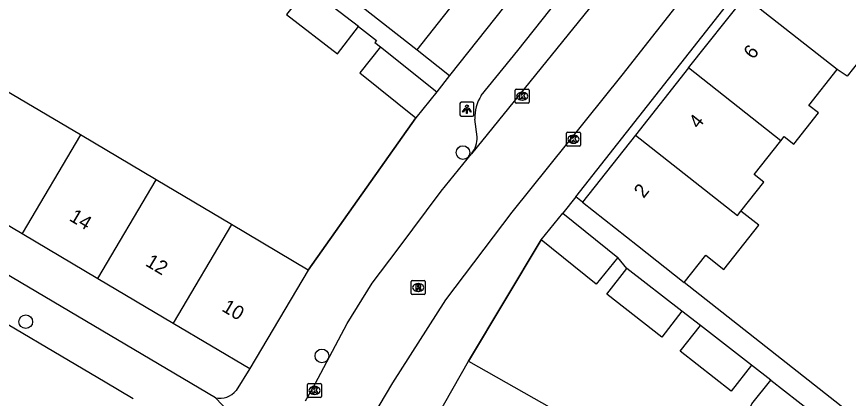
# Model space of a CAD drawing. Extents: x 160026 to 161302, y 384757 to 385701.
# Drawn here: x 160366.7 to 160426.3, y 385107 to 385134.3 of the extents above; entities that cross this region are included whole.
import ezdxf

# ---------------------------------------------------------------- set-up
doc = ezdxf.new("R2010")
doc.units = 0
for name, color, linetype in [('IMGEO_Boom', 7, 'Continuous'), ('IMGEO_Kolk', 7, 'Continuous'), ('IMGEO_Lichtpunt', 7, 'Continuous'), ('IMGEO_Muur', 7, 'Continuous'), ('IMGEO_Pand', 7, 'Continuous'), ('IMGEO_Pand_nummerreeks', 7, 'Continuous'), ('IMGEO_Rijbaan_lokaal_gesloten', 7, 'Continuous'), ('IMGEO_Rijbaan_lokaal_open', 7, 'Continuous'), ('IMGEO_Rioolput', 7, 'Continuous'), ('IMGEO_Voetpad_open', 7, 'Continuous')]:
    doc.layers.add(name, color=color, linetype=linetype)

msp = doc.modelspace()

# ---------------------------------------------------------------- linework, layer by layer
at = {"layer": 'IMGEO_Boom'}
for centre in [(160398.678, 385124.57), (160367.392, 385112.466), (160388.586, 385110.018)]:
    msp.add_circle(centre, 0.489, dxfattribs=at)
at = {"layer": 'IMGEO_Kolk'}
for p, q in [((160402.417, 385128.182), (160402.417, 385129.034)), ((160402.492, 385129.108), (160403.344, 385129.108)), ((160402.905, 385128.888), (160402.93, 385128.888)), ((160403.418, 385129.034), (160403.418, 385128.182)), ((160403.344, 385128.108), (160402.492, 385128.108)), ((160402.928, 385128.328), (160402.903, 385128.328)), ((160406.082, 385125.096), (160406.082, 385125.948)), ((160406.157, 385126.022), (160407.009, 385126.022)), ((160406.57, 385125.802), (160406.595, 385125.802)), ((160407.083, 385125.948), (160407.083, 385125.096)), ((160406.593, 385125.242), (160406.568, 385125.242)), ((160407.009, 385125.022), (160406.157, 385125.022)), ((160387.558, 385107.12), (160387.558, 385107.972)), ((160387.633, 385108.046), (160388.485, 385108.046)), ((160388.046, 385107.826), (160388.071, 385107.826)), ((160388.559, 385107.972), (160388.559, 385107.12)), ((160388.069, 385107.266), (160388.044, 385107.266)), ((160388.485, 385107.046), (160387.633, 385107.046))]:
    msp.add_line(p, q, dxfattribs=at)
for points in [[(160402.417, 385128.182), (160402.417, 385129.034)], [(160402.492, 385129.108), (160403.344, 385129.108)], [(160402.738, 385128.808), (160402.861, 385128.808), (160402.861, 385128.657), (160402.991, 385128.808), (160403.155, 385128.808), (160403.009, 385128.657), (160403.162, 385128.408), (160403.01, 385128.408), (160402.925, 385128.572), (160402.861, 385128.505), (160402.861, 385128.408), (160402.738, 385128.408), (160402.738, 385128.808)], [(160403.418, 385129.034), (160403.418, 385128.182)], [(160403.344, 385128.108), (160402.492, 385128.108)], [(160406.082, 385125.096), (160406.082, 385125.948)], [(160406.157, 385126.022), (160407.009, 385126.022)], [(160406.403, 385125.722), (160406.526, 385125.722), (160406.526, 385125.571), (160406.656, 385125.722), (160406.82, 385125.722), (160406.674, 385125.571), (160406.827, 385125.322), (160406.675, 385125.322), (160406.59, 385125.486), (160406.526, 385125.419), (160406.526, 385125.322), (160406.403, 385125.322), (160406.403, 385125.722)], [(160407.083, 385125.948), (160407.083, 385125.096)], [(160407.009, 385125.022), (160406.157, 385125.022)], [(160387.558, 385107.12), (160387.558, 385107.972)], [(160387.633, 385108.046), (160388.485, 385108.046)], [(160388.559, 385107.972), (160388.559, 385107.12)], [(160387.879, 385107.746), (160388.002, 385107.746), (160388.002, 385107.595), (160388.132, 385107.746), (160388.296, 385107.746), (160388.15, 385107.595), (160388.303, 385107.346), (160388.151, 385107.346), (160388.066, 385107.51), (160388.002, 385107.443), (160388.002, 385107.346), (160387.879, 385107.346), (160387.879, 385107.746)], [(160388.485, 385107.046), (160387.633, 385107.046)]]:
    msp.add_lwpolyline(points, dxfattribs=at)
for centre, start, end in [((160402.494, 385129.032), 91.55205, 178.44795), ((160402.494, 385129.032), 91.55205, 178.44795), ((160403.342, 385129.032), 1.55205, 88.44795), ((160403.342, 385129.032), 1.55205, 88.44795), ((160402.494, 385128.184), 181.55205, 268.44795), ((160402.494, 385128.184), 181.55205, 268.44795), ((160403.342, 385128.184), 271.55205, 358.44795), ((160403.342, 385128.184), 271.55205, 358.44795), ((160406.159, 385125.946), 91.55205, 178.44795), ((160406.159, 385125.946), 91.55205, 178.44795), ((160407.007, 385125.946), 1.55205, 88.44795), ((160407.007, 385125.946), 1.55205, 88.44795), ((160406.159, 385125.098), 181.55205, 268.44795), ((160406.159, 385125.098), 181.55205, 268.44795), ((160407.007, 385125.098), 271.55205, 358.44795), ((160407.007, 385125.098), 271.55205, 358.44795), ((160387.635, 385107.97), 91.55205, 178.44795), ((160387.635, 385107.97), 91.55205, 178.44795), ((160388.483, 385107.97), 1.55205, 88.44795), ((160388.483, 385107.97), 1.55205, 88.44795), ((160387.635, 385107.122), 181.55205, 268.44795), ((160387.635, 385107.122), 181.55205, 268.44795), ((160388.483, 385107.122), 271.55205, 358.44795), ((160388.483, 385107.122), 271.55205, 358.44795)]:
    msp.add_arc(centre, 0.0765, start, end, dxfattribs=at)
for centre, major_axis, ratio, start_param, end_param in [((160402.904, 385128.608), (-0.387, 0.002), 0.722429, 4.712389, 7.853982), ((160402.929, 385128.608), (-0.39, 0.002), 0.717154, 1.570796, 4.712389), ((160406.569, 385125.522), (-0.387, 0.002), 0.722429, 4.712389, 7.853982), ((160406.594, 385125.522), (-0.39, 0.002), 0.717154, 1.570796, 4.712389), ((160388.045, 385107.546), (-0.387, 0.002), 0.722429, 4.712389, 7.853982), ((160388.07, 385107.546), (-0.39, 0.002), 0.717154, 1.570796, 4.712389)]:
    msp.add_ellipse(centre, major_axis=major_axis, ratio=ratio, start_param=start_param, end_param=end_param, dxfattribs=at)
at = {"layer": 'IMGEO_Lichtpunt'}
for p, q in [((160398.464, 385128.079), (160398.464, 385127.272)), ((160398.464, 385128.079), (160398.464, 385127.272)), ((160399.366, 385128.174), (160398.558, 385128.174)), ((160399.366, 385128.174), (160398.558, 385128.174)), ((160399.46, 385127.272), (160399.46, 385128.079)), ((160399.46, 385127.272), (160399.46, 385128.079)), ((160398.558, 385127.178), (160399.366, 385127.178)), ((160398.558, 385127.178), (160399.366, 385127.178))]:
    msp.add_line(p, q, dxfattribs=at)
for points in [[(160398.838, 385127.743), (160398.877, 385127.715), (160398.689, 385127.453), (160398.651, 385127.48), (160398.838, 385127.743)], [(160398.94, 385127.695), (160398.987, 385127.695), (160398.987, 385127.373), (160398.94, 385127.373), (160398.94, 385127.695)], [(160399.05, 385127.715), (160399.088, 385127.742), (160399.275, 385127.48), (160399.236, 385127.452), (160399.05, 385127.715)]]:
    msp.add_lwpolyline(points, dxfattribs=at)
msp.add_circle((160398.963, 385127.877), 0.0994, dxfattribs=at)
for centre, start, end in [((160398.558, 385128.079), 90, 180), ((160398.558, 385128.079), 90, 180), ((160399.366, 385128.079), 0, 90), ((160399.366, 385128.079), 0, 90), ((160398.558, 385127.272), 180, 270), ((160398.558, 385127.272), 180, 270), ((160399.366, 385127.272), 270, 0), ((160399.366, 385127.272), 270, 360)]:
    msp.add_arc(centre, 0.0946, start, end, dxfattribs=at)
at = {"layer": 'IMGEO_Muur'}
for points in [[(160387.606, 385116.164), (160395.316, 385127.065)], [(160399.08, 385109.636), (160404.28, 385118.318)]]:
    msp.add_lwpolyline(points, dxfattribs=at)
at = {"layer": 'IMGEO_Pand'}
for points in [[(160388.899, 385136.994), (160391.469, 385134.988), (160395.41, 385131.912)], [(160387.574, 385136.374), (160386.049, 385134.443), (160389.705, 385131.638), (160391.203, 385133.589)], [(160391.203, 385133.589), (160387.574, 385136.374)], [(160395.41, 385131.912), (160399.257, 385136.84)], [(160414.825, 385130.622), (160418.852, 385135.725)], [(160425.462, 385130.507), (160418.852, 385135.725)], [(160429.474, 385135.723), (160427.258, 385132.915), (160427.989, 385132.338), (160426.18, 385130.045), (160425.462, 385130.507)], [(160392.78, 385132.125), (160391.3, 385130.27), (160395.316, 385127.065)], [(160392.78, 385132.125), (160396.797, 385128.92)], [(160414.825, 385130.622), (160411.029, 385125.813)], [(160421.417, 385125.418), (160414.825, 385130.622)], [(160421.417, 385125.418), (160421.658, 385125.723), (160422.352, 385125.174), (160424.112, 385127.404), (160423.435, 385127.938), (160425.462, 385130.507)], [(160371.303, 385125.827), (160366.008, 385128.966)], [(160396.797, 385128.92), (160395.316, 385127.065)], [(160371.303, 385125.827), (160367.143, 385118.768)], [(160376.718, 385122.618), (160371.303, 385125.827)], [(160411.029, 385125.813), (160407.24, 385121.013)], [(160411.029, 385125.813), (160418.32, 385120.058), (160418.565, 385120.369)], [(160418.565, 385120.369), (160420.213, 385122.455), (160419.514, 385123.007), (160421.417, 385125.418)], [(160372.558, 385115.558), (160376.718, 385122.618)], [(160382.108, 385119.423), (160376.718, 385122.618)], [(160361.848, 385121.906), (160367.143, 385118.768)], [(160407.24, 385121.013), (160411.164, 385117.915), (160414.516, 385115.27)], [(160414.516, 385115.27), (160416.06, 385117.227), (160417.35, 385116.209), (160419.84, 385119.363), (160418.565, 385120.369)], [(160404.28, 385118.318), (160405.818, 385120.228)], [(160405.818, 385120.228), (160409.747, 385117.063)], [(160382.108, 385119.423), (160377.947, 385112.363)], [(160387.606, 385116.164), (160382.108, 385119.423)], [(160367.143, 385118.768), (160372.558, 385115.558)], [(160409.747, 385117.063), (160408.208, 385115.153), (160404.28, 385118.318)], [(160387.606, 385116.164), (160383.427, 385109.115)], [(160414.35, 385113.209), (160412.914, 385111.361), (160408.969, 385114.427), (160410.406, 385116.271)], [(160414.35, 385113.209), (160410.406, 385116.271)], [(160372.558, 385115.558), (160377.947, 385112.363)], [(160377.947, 385112.363), (160383.427, 385109.115)], [(160419.313, 385109.352), (160417.877, 385107.504), (160414.212, 385110.352), (160415.669, 385112.184)], [(160419.313, 385109.352), (160415.669, 385112.184)], [(160395.003, 385102.463), (160399.08, 385109.636)], [(160399.08, 385109.636), (160405.009, 385106.266)], [(160424.617, 385105.23), (160423.181, 385103.383), (160419.269, 385106.422), (160419.357, 385106.577), (160420.704, 385108.271)], [(160420.704, 385108.271), (160424.617, 385105.23)]]:
    msp.add_lwpolyline(points, dxfattribs=at)
at = {"layer": 'IMGEO_Rijbaan_lokaal_gesloten'}
msp.add_lwpolyline([(160333.972, 385131.862), (160342.253, 385126.595), (160343.306, 385125.926), (160345.516, 385124.585), (160353.245, 385119.896), (160362.963, 385114.135), (160373.082, 385108.155), (160375.076, 385106.975)], dxfattribs=at)
at = {"layer": 'IMGEO_Rijbaan_lokaal_open'}
for points in [[(160448.926, 385179.255), (160441.301, 385169.642), (160436.8, 385163.928), (160428.03, 385152.903), (160419.879, 385142.636), (160410.04, 385130.111), (160402.173, 385120.293), (160397.425, 385114.032), (160393.624, 385108.1), (160392.655, 385106.45), (160391.867, 385105.123), (160391.174, 385103.832)], [(160442.328, 385178.803), (160425.568, 385157.508), (160410.374, 385138.189), (160399.293, 385124.481)], [(160387.414, 385106.8), (160388.11, 385108.029), (160390.397, 385112.327), (160392.191, 385115.214), (160394.033, 385117.675), (160397.127, 385121.806), (160399.293, 385124.481)]]:
    msp.add_lwpolyline(points, dxfattribs=at)
at = {"layer": 'IMGEO_Rioolput'}
for p, q in [((160394.975, 385114.485), (160394.975, 385115.337)), ((160395.05, 385115.411), (160395.902, 385115.411)), ((160395.463, 385115.191), (160395.488, 385115.191)), ((160395.976, 385115.337), (160395.976, 385114.485)), ((160395.902, 385114.411), (160395.05, 385114.411)), ((160395.486, 385114.631), (160395.461, 385114.631))]:
    msp.add_line(p, q, dxfattribs=at)
for points in [[(160394.975, 385114.485), (160394.975, 385115.337)], [(160395.05, 385115.411), (160395.902, 385115.411)], [(160395.564, 385115.109), (160395.312, 385115.111), (160395.312, 385114.711)], [(160395.49, 385115.03), (160395.436, 385115.03), (160395.436, 385114.949)], [(160395.436, 385114.949), (160395.488, 385114.949)], [(160395.976, 385115.337), (160395.976, 385114.485)], [(160395.902, 385114.411), (160395.05, 385114.411)], [(160395.312, 385114.711), (160395.436, 385114.711), (160395.436, 385114.873), (160395.447, 385114.873)], [(160395.494, 385114.844), (160395.565, 385114.711), (160395.705, 385114.711), (160395.64, 385114.837)]]:
    msp.add_lwpolyline(points, dxfattribs=at)
for centre, radius, start, end in [((160395.052, 385115.335), 0.0765, 91.55205, 178.44795), ((160395.052, 385115.335), 0.0765, 91.55205, 178.44795), ((160395.472, 385115.138), 0.19, 274.7715, 282.96867), ((160395.496, 385114.934), 0.0964, 77.00612, 93.18647), ((160395.51, 385114.991), 0.0378, 276.66336, 79.67722), ((160395.563, 385114.999), 0.109, 350.36119, 89.41601), ((160395.561, 385114.999), 0.112, 277.58423, 350.98172), ((160395.9, 385115.335), 0.0765, 1.55205, 88.44795), ((160395.9, 385115.335), 0.0765, 1.55205, 88.44795), ((160395.052, 385114.487), 0.0765, 181.55205, 268.44795), ((160395.052, 385114.487), 0.0765, 181.55205, 268.44795), ((160395.446, 385114.82), 0.0533, 26.02933, 88.69889), ((160395.545, 385114.784), 0.108, 29.51342, 73.79051), ((160395.9, 385114.487), 0.0765, 271.55205, 358.44795), ((160395.9, 385114.487), 0.0765, 271.55205, 358.44795)]:
    msp.add_arc(centre, radius, start, end, dxfattribs=at)
for centre, major_axis, ratio, start_param, end_param in [((160395.462, 385114.911), (-0.387, 0.002), 0.722429, 4.712389, 7.853982), ((160395.487, 385114.911), (-0.39, 0.002), 0.717154, 1.570796, 4.712389)]:
    msp.add_ellipse(centre, major_axis=major_axis, ratio=ratio, start_param=start_param, end_param=end_param, dxfattribs=at)
at = {"layer": 'IMGEO_Voetpad_open'}
for points in [[(160399.991, 385128.66), (160402.593, 385131.871), (160407.729, 385138.373), (160421.792, 385156.244), (160433.04, 385170.374), (160436.32, 385174.419), (160438.498, 385177.186)], [(160421.238, 385159.843), (160417.417, 385154.927), (160397.718, 385130.082)], [(160406.744, 385121.404), (160422.407, 385141.3)], [(160391.203, 385133.589), (160392.493, 385132.599), (160392.37, 385132.439), (160392.78, 385132.125)], [(160395.41, 385131.912), (160397.718, 385130.082)], [(160380.959, 385107.006), (160350.683, 385124.926), (160341.364, 385130.768)], [(160397.718, 385130.082), (160396.797, 385128.92)], [(160395.316, 385127.065), (160387.606, 385116.164)], [(160399.688, 385125.693), (160399.536, 385126.966)], [(160406.744, 385121.404), (160405.818, 385120.228)], [(160407.24, 385121.013), (160406.744, 385121.404)], [(160404.28, 385118.318), (160399.08, 385109.636)], [(160410.406, 385116.271), (160409.747, 385117.063)], [(160429.309, 385105.761), (160428.436, 385104.286), (160414.516, 385115.27)], [(160415.669, 385112.184), (160414.35, 385113.209)], [(160383.427, 385109.115), (160382.455, 385107.541)], [(160420.704, 385108.271), (160419.313, 385109.352)], [(160380.959, 385107.006), (160383.927, 385103.925)]]:
    msp.add_lwpolyline(points, dxfattribs=at)
for centre, radius, start, end in [((160402.324, 385127.125), 2.792, 146.66098, 183.26998), ((160397.839, 385125.625), 1.851, 321.80201, 2.09563), ((160381.244, 385108.568), 1.588, 259.65404, 319.70213)]:
    msp.add_arc(centre, radius, start, end, dxfattribs=at)

# ---------------------------------------------------------------- texts
at = {"layer": 'IMGEO_Pand_nummerreeks'}
for s, rotation, p in [('6', 51.71619, (160419.449, 385131.188)), ('4', 51.71517, (160415.527, 385126.219)), ('2', 51.71517, (160411.604, 385121.248)), ('14', 329.34213, (160370.443, 385119.741)), ('12', 329.34213, (160375.895, 385116.51)), ('10', 329.34213, (160381.355, 385113.273))]:
    msp.add_text(s, height=1, rotation=rotation, dxfattribs=at).set_placement(p)

doc.saveas('drawing.dxf')
